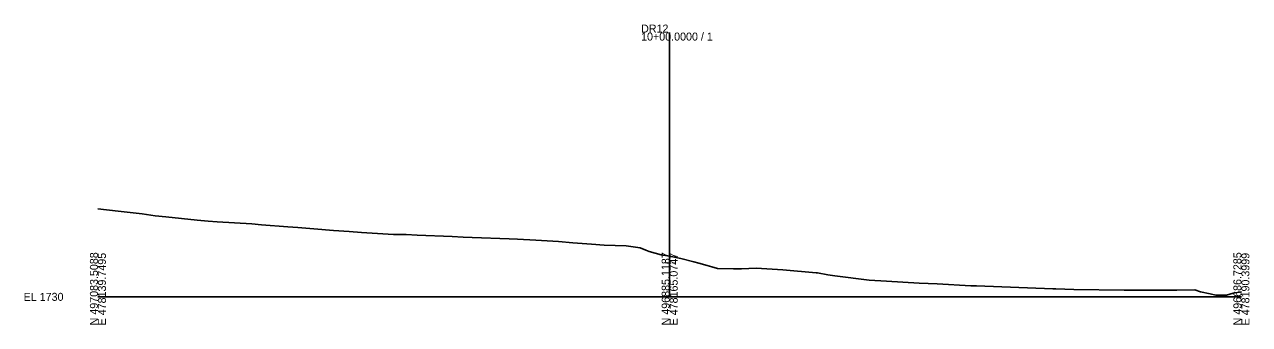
# Model space of a CAD drawing. Extents: x -26 to 403, y -10 to 3574.
# Drawn here: x -25.7 to 402.8, y -9.7 to 95.4 of the extents above; entities that cross this region are included whole.
import ezdxf

# ---------------------------------------------------------------- set-up
doc = ezdxf.new("R2010")
doc.units = 0
for name, color, linetype in [('Exist Cross Section Cell', 7, 'Continuous'), ('Exist XS Center Line Elevation Label', 7, 'Continuous'), ('Exist XS Ground Line', 7, 'Continuous'), ('Scratch_Level_5', 7, 'Continuous')]:
    doc.layers.add(name, color=color, linetype=linetype)

msp = doc.modelspace()

# ---------------------------------------------------------------- linework, layer by layer
at = {"layer": 'Exist Cross Section Cell'}
for p, q in [((200, 0), (200, 92.54)), ((0, 0), (200, 0)), ((200, 0), (400, 0))]:
    msp.add_line(p, q, dxfattribs=at)
at = {"layer": 'Exist XS Ground Line'}
msp.add_lwpolyline([(0, 30.85), (7.02, 29.95), (15.43, 29.02), (20.06, 28.37), (23.77, 28), (34.67, 26.84), (38.51, 26.55), (41.74, 26.21), (53.83, 25.51), (57.16, 25.26), (66.47, 24.5), (69.88, 24.23), (75.54, 23.77), (82.43, 23.26), (87.86, 22.83), (92.25, 22.57), (103.36, 21.86), (107.87, 21.8), (111.67, 21.55), (123.95, 21.08), (127.71, 20.88), (130.95, 20.78), (143.84, 20.29), (146.75, 20.14), (153.16, 19.83), (161.1, 19.4), (166.11, 18.91), (172.6, 18.42), (177.11, 18.11), (184.82, 17.84), (189.65, 17.15), (191.72, 16.37), (192.83, 15.86), (197.06, 14.77), (200, 14.2), (203.89, 13.45), (208.46, 12.28), (210.26, 11.85), (213.16, 10.92), (214.71, 10.51), (216.75, 9.96), (222.32, 9.82), (224.65, 9.79), (225.11, 9.82), (230.25, 10.03), (239.57, 9.43), (251.3, 8.42), (251.71, 8.43), (255.33, 7.76), (257.74, 7.4), (269.84, 5.8), (275.86, 5.49), (287.27, 4.79), (293.63, 4.58), (305.3, 3.91), (306.23, 3.88), (307.33, 3.84), (334.09, 2.86), (335.04, 2.82), (341.42, 2.6), (359.01, 2.33), (366.89, 2.32), (373.42, 2.36), (377.42, 2.33), (383.69, 2.41), (385.67, 1.76), (389.06, 1.1), (391.11, 0.63), (391.47, 0.64), (394.8, 0.53), (397.07, 1.25), (400, 1.81)], dxfattribs=at)
at = {"layer": 'Scratch_Level_5'}
msp.add_lwpolyline([(0, 30.85), (7.02, 29.95), (15.43, 29.02), (20.06, 28.37), (23.77, 28), (34.67, 26.84), (38.51, 26.55), (41.74, 26.21), (53.83, 25.51), (57.16, 25.26), (66.47, 24.5), (69.88, 24.23), (75.54, 23.77), (82.43, 23.26), (87.86, 22.83), (92.25, 22.57), (103.36, 21.86), (107.87, 21.8), (111.67, 21.55), (123.95, 21.08), (127.71, 20.88), (130.95, 20.78), (143.84, 20.29), (146.75, 20.14), (153.16, 19.83), (161.1, 19.4), (166.11, 18.91), (172.6, 18.42), (177.11, 18.11), (184.82, 17.84), (189.65, 17.15), (191.72, 16.37), (192.83, 15.86), (197.06, 14.77), (200, 14.2), (203.89, 13.45), (208.46, 12.28), (210.26, 11.85), (213.16, 10.92), (214.71, 10.51), (216.75, 9.96), (222.32, 9.82), (224.65, 9.79), (225.11, 9.82), (230.25, 10.03), (239.57, 9.43), (251.3, 8.42), (251.71, 8.43), (255.33, 7.76), (257.74, 7.4), (269.84, 5.8), (275.86, 5.49), (287.27, 4.79), (293.63, 4.58), (305.3, 3.91), (306.23, 3.88), (307.33, 3.84), (334.09, 2.86), (335.04, 2.82), (341.42, 2.6), (359.01, 2.33), (366.89, 2.32), (373.42, 2.36), (377.42, 2.33), (383.69, 2.41), (385.67, 1.76), (389.06, 1.1), (391.11, 0.63), (391.47, 0.64), (394.8, 0.53), (397.07, 1.25), (400, 1.81)], dxfattribs=at)
msp.add_lwpolyline([(0, 30.85), (7.02, 29.95), (15.43, 29.02), (20.06, 28.37), (23.77, 28), (34.67, 26.84), (38.51, 26.55), (41.74, 26.21), (53.83, 25.51), (57.16, 25.26), (66.47, 24.5), (69.88, 24.23), (75.54, 23.77), (82.43, 23.26), (87.86, 22.83), (92.25, 22.57), (103.36, 21.86), (107.87, 21.8), (111.67, 21.55), (123.95, 21.08), (127.71, 20.88), (130.95, 20.78), (143.84, 20.29), (146.75, 20.14), (153.16, 19.83), (161.1, 19.4), (166.11, 18.91), (172.6, 18.42), (177.11, 18.11), (184.82, 17.84), (189.65, 17.15), (191.72, 16.37), (192.83, 15.86), (197.06, 14.77), (200, 14.2), (203.89, 13.45), (208.46, 12.28), (210.26, 11.85), (213.16, 10.92), (214.71, 10.51), (216.75, 9.96), (222.32, 9.82), (224.65, 9.79), (225.11, 9.82), (230.25, 10.03), (239.57, 9.43), (251.3, 8.42), (251.71, 8.43), (255.33, 7.76), (257.74, 7.4), (269.84, 5.8), (275.86, 5.49), (287.27, 4.79), (293.63, 4.58), (305.3, 3.91), (306.23, 3.88), (307.33, 3.84), (334.09, 2.86), (335.04, 2.82), (341.42, 2.6), (359.01, 2.33), (366.89, 2.32), (373.42, 2.36), (377.42, 2.33), (383.69, 2.41), (385.67, 1.76), (389.06, 1.1), (391.11, 0.63), (391.47, 0.64), (394.8, 0.53), (397.07, 1.25), (400, 1.81)], dxfattribs=at)

# ---------------------------------------------------------------- texts
at = {"layer": 'Exist Cross Section Cell'}
for s, p in [('DR12', (190, 92.54)), ('10+00.0000 / 1', (190, 89.74)), ('EL 1730', (-26, -1.4))]:
    msp.add_text(s, height=2.8, dxfattribs=at).set_placement(p)
for s, p in [('N 497083.5088', (0, -10)), ('E 478139.7495', (2.8, -10)), ('N 496885.1187', (200, -10)), ('E 478165.0747', (202.8, -10)), ('N 496686.7285', (400, -10)), ('E 478190.3999', (402.8, -10))]:
    msp.add_text(s, height=2.8, rotation=90, dxfattribs=at).set_placement(p)
at = {"layer": 'Exist XS Center Line Elevation Label'}
msp.add_text('1744.20', height=0.75, dxfattribs=at).set_placement((198.26, 11.45))

doc.saveas('drawing.dxf')
